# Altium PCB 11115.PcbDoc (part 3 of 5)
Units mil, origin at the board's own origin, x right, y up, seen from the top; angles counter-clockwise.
Board outline 4800 x 3500.1 mil, 4 copper layers (Top Layer, Layer 2, Layer 3, Bottom Layer), stack 61.6 mil thick; 316 components, 224 nets, 954 pads, 623 vias.
Unrouted connection lines stored in the file: 268.
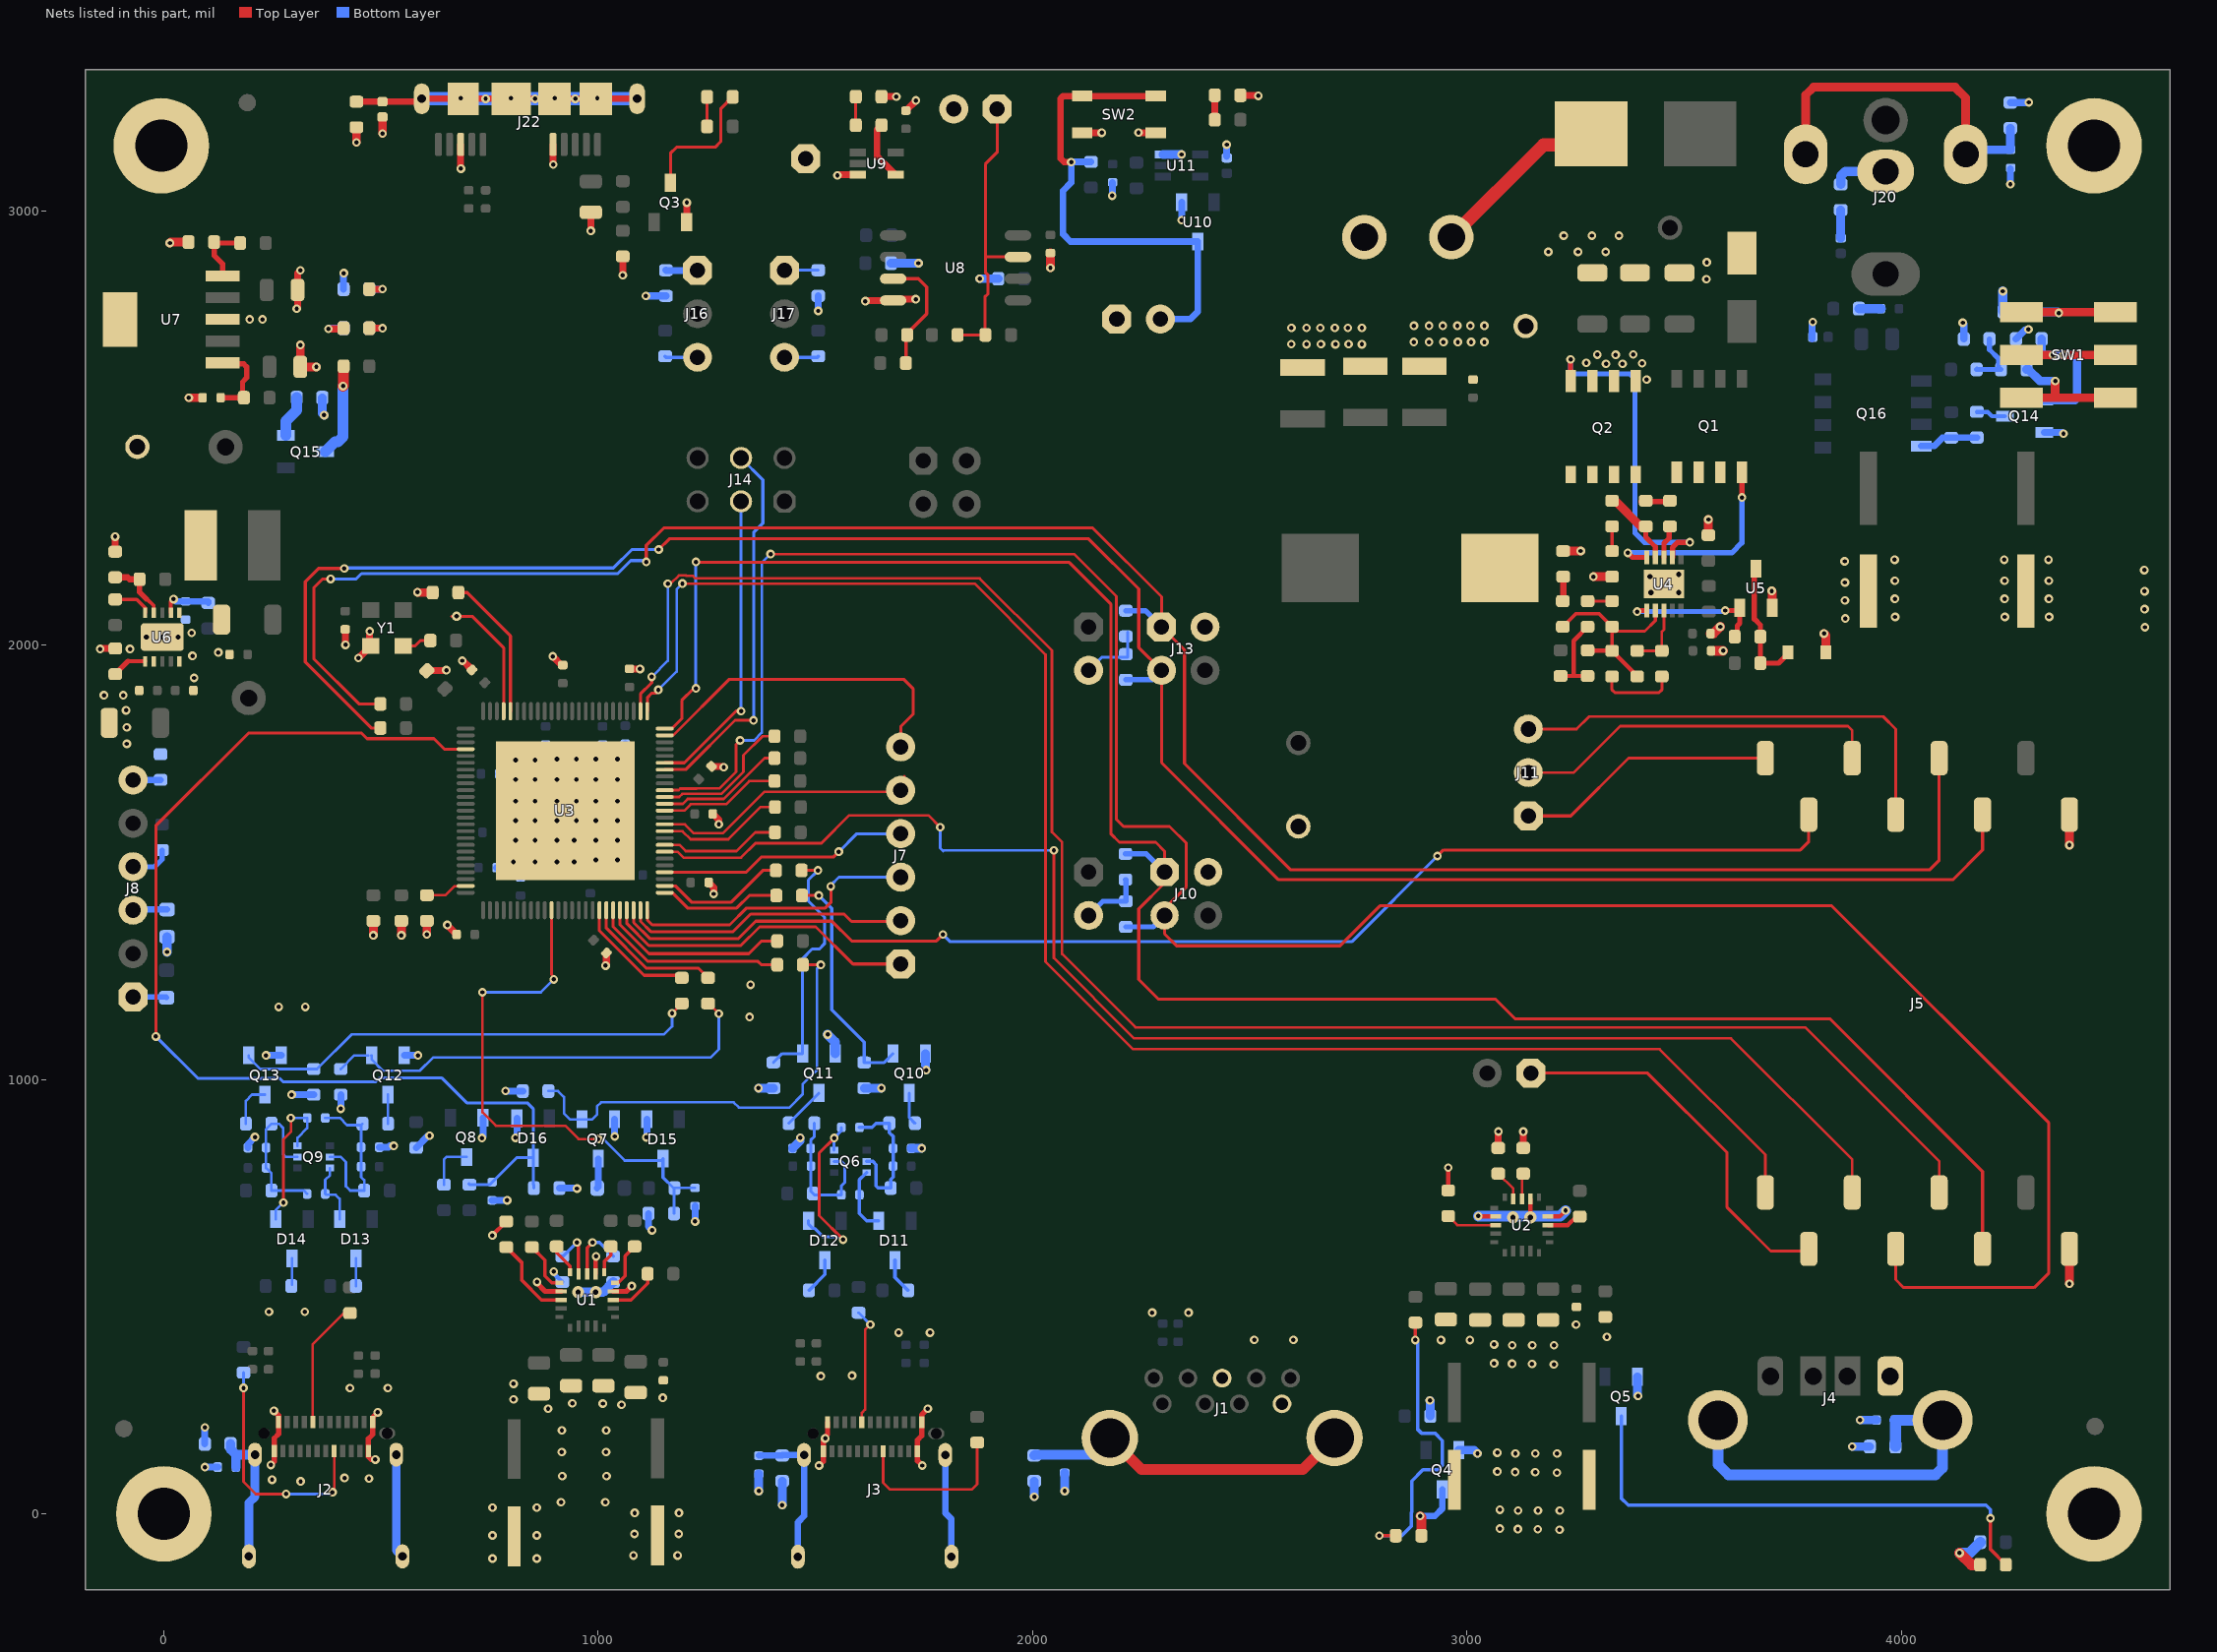
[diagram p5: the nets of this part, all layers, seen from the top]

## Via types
v1: diameter 20, hole 10, Top Layer to Bottom Layer, tented both sides, 576 vias
v2: diameter 23, hole 11, Top Layer to Bottom Layer, 36 vias
v3: diameter 20, hole 12, Top Layer to Bottom Layer, 7 vias
v4: diameter 27.56, hole 11.81, Top Layer to Bottom Layer, 4 vias

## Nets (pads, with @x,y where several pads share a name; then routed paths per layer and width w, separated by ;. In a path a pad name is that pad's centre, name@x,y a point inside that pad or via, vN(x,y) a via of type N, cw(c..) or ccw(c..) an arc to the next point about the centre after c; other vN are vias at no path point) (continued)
DP1_VBUS_MON: C72.1 D16.3 R76.1 R82.2 U3.4 | length 2605
  Top Layer w7: v1(-18.23,1099.34) -18.23,1584.34 195.31,1797.89 455,1797.89 468.07,1784.82 621.82,1784.82 645.77,1760.87 U3.4@695.05,1760.87
  Bottom Layer w7: v1(-18.23,1099.34) 78.56,1002.54 266.75,1002.54 274.56,994.74 487.78,994.74 496.7,1003.66 640.39,1003.66 697.66,946.39 836.77,946.39 850.44,932.72 D16.3@850.44,820.03 ; R76.1@702.08,760.76 R76.1@703.65,759.2 ; R76.1@703.65,758.08 750.3,758.08 C72.1@755.95,763.73 812.25,820.03 D16.3@850.44,820.03 ; R82.2@851.85,750.16 851.85,758.08 850.44,759.49 D16.3@850.44,820.03
DP1_VCONN1: Q13.1 R15.1 R94.2 | length 1093.8
  Top Layer w6: v1(1170.21,1152.37) 1169.7,1152.37 R15.1@1192.54,1175.21
  Bottom Layer w6: Q13.1@195.68,1055.76 195.68,1050.7 222.11,1024.27 R94.2@345.15,1024.27 352.71,1024.27 432.28,1103.83 1151.44,1103.83 1170.21,1122.61 v1(1170.21,1152.37)
DP1_VCONN2: Q12.1 R16.1 R93.2 | length 1034.1
  Top Layer w6: R16.1@1253.06,1175.21 1254.45,1175.21 v1(1277.87,1151.79)
  Bottom Layer w6: R93.2@407.44,1024.27 438.94,1055.76 Q12.1@470.33,1055.76 ; Q12.1@478.31,1055.08 Q12.1@478.99,1055.76 478.99,1045.99 504.69,1020.29 589.62,1020.29 620.03,1050.7 1258.56,1050.7 1277.87,1070 v1(1277.87,1151.79) v1@1277.87,1152.82
DP2_DISCHARGE: Q7.1 R17.1 R92.2 | length 1035.8
  Top Layer w6: R17.1@1471.27,1264.24 v1(1512.67,1264.24)
  Bottom Layer w6: R92.2@885.46,973.67 907.42,973.67 921.31,959.77 921.31,922.12 934.98,908.45 Q7.1@962.83,908.45 986.56,908.45 997.45,919.34 997.45,937.71 1007.19,947.44 1312.07,947.44 1323.83,935.68 1440.67,935.68 1470.9,965.91 1470.9,988.83 1489.95,1007.89 1503.83,1021.77 1503.83,1255.4 v1(1512.67,1264.24)
DP2_VBUS_MON: C70.1 D15.3 R75.2 R80.1 U3.36 | length 1263.9
  Top Layer w6: v1(733.62,1201.02) 733.62,924.26 764.42,893.45 924.57,893.45 954.85,863.17 v1(1000.23,863.17) ; U3.36@892.69,1390 892.69,1242.16 897.72,1237.12 v1(897.72,1230.64)
  Bottom Layer w6: v1(733.62,1201.02) 868.1,1201.02 v1(897.72,1230.64) ; v1(1000.23,863.17) 1011.64,863.17 1061.15,813.66 1145.15,813.66 D15.3@1149.39,817.9 ; R75.2@1174.73,691.52 R80.1@1174.73,748.98 ; R80.1@1175.91,750.16 1176.29,750.54 C70.1@1223.18,750.54
  Bottom Layer w7: D15.3@1149.39,817.9 1149.39,774.32 1174.73,748.98 R80.1@1175.91,750.16
DP2_VCONN1: Q10.1 R22.1 R90.2 | length 541.4
  Top Layer w7: R22.1@1469.24,1423.77 v1(1508.16,1423.77)
  Bottom Layer w7: v1(1508.16,1423.77) 1537.83,1394.09 1537.83,1160.6 1612.48,1085.95 R90.2@1612.48,1039.39 1658.67,1039.39 Q10.1@1678.94,1059.66
DP2_VCONN2: Q11.1 R23.1 R91.2 | length 591.1
  Top Layer w7: R23.1@1468.39,1481.64 v1(1506.19,1481.64)
  Bottom Layer w7: R91.2@1403.43,1039.39 1423.71,1059.66 Q11.1@1470.75,1059.66 1470.75,1278.88 1492.65,1300.78 1509.45,1300.78 1520.87,1312.2 1520.87,1313.74 1521.7,1314.56 1521.7,1373.16 1484.14,1410.71 1484.14,1459.6 v1(1506.19,1481.64)
EARTH_DC: C93.1 J20.0 R102.1 | length 810.9
  Top Layer w20: J20.0@3780.02,3130.32 3780.02,3266.93 3798.08,3285 4124.15,3285 4148.28,3260.87 J20.0@4148.28,3130.32
  Bottom Layer w20: J20.0@4148.28,3130.32 4158.83,3140.87 C93.1@4252,3140.87 4251.28,3141.59 R102.1@4251.28,3190.47
EARTH_P0: C61.2 J22.0 R57.2 | length 1145.1
  Top Layer w15: R57.2@443.5,3251.65 C61.2@503.5,3251.65 587.07,3251.65 J22.0@593.75,3258.33 J22.0@689.42,3258.33 v1(741,3258.33) 799.3,3258.33 J22.0@799.65,3258.33 v1(854.65,3258.33) J22.0@900.05,3258.33 v1(947.45,3258.33) J22.0@994.54,3258.33 J22.0@1089.81,3258.33
  Bottom Layer w30: J22.0@593.75,3258.33 v1(741,3258.33) v1(854.65,3258.33) v1(947.45,3258.33) J22.0@1089.81,3258.33
  other v1: 683.8,3259.39 799.3,3259.39 899.69,3259.39 998.12,3259.39
EARTH_P1: C64.2 J2.25 R65.1 | length 582.6
  Bottom Layer w20: J2.25@195.87,-97.87 195.87,25.15 210.05,39.33 J2.25@210.05,136.39 ; J2.25@535.24,136.39 535.24,-83.69 J2.25@549.42,-97.87
  Bottom Layer w22: R65.1@153.68,160.9 153.68,148.88 166.17,136.39 ; C64.2@165.88,107.76 165.88,136.1 166.17,136.39 ; J2.25@210.05,136.39 166.17,136.39
EARTH_P2: C63.2 J3.25 R63.1 | length 585.1
  Bottom Layer w15: C63.2@1369.87,134.1 1423.28,134.1 R63.1@1423.71,134.53 1424.91,135.73 J3.25@1474.05,135.73 1474.05,-5 1459.87,-19.17 J3.25@1459.87,-98.52 ; J3.25@1799.24,135.73 1799.24,2.17 1813.42,-12.01 J3.25@1813.42,-98.52
EARTH_P3: C62.2 J1.0 R62.2 | length 768.2
  Top Layer w25: J1.0@2177.98,174.73 2250.93,101.79 2622.36,101.79 J1.0@2695.31,174.73
  Bottom Layer w22: R62.2@2004.15,134.53 2005.91,136.28 C62.2@2074.15,136.28 2139.54,136.28 J1.0@2177.98,174.73
EARTH_P4: C65.2 J4.0 R64.2 | length 973.5
  Top Layer w25: J4.0@4095.31,216 J4.0@4134.31,255
  Bottom Layer w25: J4.0@3577.98,216 3577.98,114.09 3602.74,89.33 4078.48,89.33 4095.31,106.16 J4.0@4095.31,216 C65.2@3985.02,216 3986.75,214.27 R64.2@3986.75,155
FB3V3: R109.1 R110.2 U7.5 | length 146.8
  Top Layer w12: U7.5@135.67,2850.34 135.67,2877.74 116.01,2897.4 R110.2@116.01,2928.32 118.21,2926.12 R109.1@175.78,2926.12
FB5V: C52.2 C54.1 R47.2 R48.2 R101.2 U4.2 | length 455.7
  Top Layer w7: 3334.21,2026.88 3334.21,2031.55 3342.34,2031.55 3343.01,2032.23 3409.84,2032.23 3434.02,2056.41 U4.2@3434.02,2080.03
  Top Layer w8: R101.2@3220.84,2042.63 3250.37,2072.16 3304.68,2072.16 C54.1@3334.21,2042.63 ; R47.2@3334.21,1987.21 3334.21,2026.88
  Top Layer w10: R48.2@3277.98,1988.39 3279.16,1987.21 R47.2@3334.21,1987.21 3392.15,1929.27 C52.2@3392.15,1928.15
FBVCORE: R112.1 R119.2 U6.4 | length 149.3
  Top Layer w9: -39.82,2106.31 -38.51,2106.31 -23.09,2090.89 U6.4@-23.09,2074.87
  Top Layer w12: R112.1@-55.69,2151.97 -55.69,2122.18 -39.82,2106.31
  Top Layer w15: R119.2@-111.77,2156.44 -83,2156.44 -78.53,2151.97 R112.1@-55.69,2151.97
GND: C1.2 C2.2 C3.2 C4.2 C5.1 C6.2 C7.1 C8.2 C13.1 C16.1 C17.2 C18.2 C19.1 C20.1 C21.2 C22.2 C23.2 C24.2 C25.2 C26.1 C29.1 C30.2 C31.2 C32.2 C33.1 C34.1 C35.1 C36.1 C37.1 C38.1 C39.1 C40.1 C41.2 C42.2 C43.1 C44.2 C46.1 C47.1 C48.1 C49.1 C50.1 C53.1 C56.1 C59.1 C60.2 C61.1 C62.1 C63.1 C64.1 C65.1 C70.2 C72.2 C78.1 C79.1 C80.1 C81.1 C84.2 C85.2 C86.2 C87.2 C88.2 C89.2 C90.2 C91.2 C92.2 C93.2 C94.1 C95.1 C96.1 C97.1 C98.1 C99.1 C100.2 C101.1 D3.1 D4.1 D6.2 D9.2 D10.2 D15.1 D16.1 J1.4 J1.7 J2.A1 J2.A12 J2.B1 J2.B12 J3.A1 J3.A12 J3.B1 J3.B12 J4.4 J5.8 J5.9 J10.2 J13.2 J18.1 J19.2 J20.2 J21.1 J22.5 J22.8 J23.2 MH1.1 MH2.1 MH3.1 MH4.1 Q2.1 Q2.2 Q2.3 Q3.2 Q4.2 Q5.2 Q7.2 Q8.2 Q10.2 Q11.2 Q12.2 Q13.2 Q14.2 R4.1 R6.1 R11.1 R13.2 R14.2 R19.2 R20.2 R21.2 R31.1 R39.1 R44.2 R45.1 R46.1 R54.1 R57.1 R62.1 R63.2 R64.1 R65.2 R66.1 R71.2 R72.2 R75.1 R82.1 R85.1 R90.1 R91.1 R92.1 R93.1 R94.1 R96.2 R102.2 R103.1 R104.1 R110.1 R113.1 R114.1 R115.1 R116.1 R117.1 R119.1 R125.2 SW2.1 SW2.2 TP2.1 TP6.1 TP8.1 U1.2 U1.14 U1.17 U2.2 U2.14 U2.17 U3.101 U4.11 U5.2 U6.7 U6.10 U6.11 U7.3 U7.6 U8.4 U9.3 U10.1 U11.3 Y1.2 | length 5890.1
  Top Layer w10: v1(756.44,641.21) 788.44,673.22 R6.1@788.44,673.39 ; U1.17@994.33,552.74 994.33,592.2 v1(995.1,592.97) ; R11.1@2957.13,744.72 v1(2957.13,797.22) ; v1(3026.32,685.68) 3027.31,684.69 U2.2@3066.61,684.69 ; v4(3146.33,682.72) U2.17@3146.33,725.04 ; U2.14@3186.69,684.69 3213.52,684.69 v1(3227.3,698.47)
  Top Layer w12: v1(246.65,112.76) 254.54,120.65 J2.B12@254.54,144.65 254.54,174.09 264.38,183.93 J2.A1@264.38,211.58 264.38,226.39 v1(253.65,237.13) ; v1(486.86,125.14) 477.56,125.14 471.07,131.63 J2.B1@471.07,144.65 471.07,173.1 480.91,182.95 J2.A12@480.91,211.58 480.91,222 v1(492.65,233.73) ; v1(859.33,533.91) 859.33,531.08 878.03,512.38 U1.2@914.6,512.38 ; U1.14@1034.68,512.38 1065.27,512.38 v1(1077.44,524.54) ; v1(1508.76,111.24) 1518.54,121.02 J3.B12@1518.54,144 1518.54,173.12 1528.38,182.97 J3.A1@1528.38,210.93 ; v1(1746.17,111.24) 1735.07,122.34 J3.B1@1735.07,144 1735.07,169.96 1744.91,179.81 J3.A12@1744.91,210.93 1744.91,228.05 v1@1759.65,242.79
  Top Layer w16: v1(-146.46,1991.45) -145.31,1992.59 C99.1@-111.77,1992.59 ; v1(-111.93,2250) -111.77,2249.84 R119.1@-111.77,2215.49 ; v1(305.97,2775) 307.94,2776.97 C94.1@307.94,2818.13 307.94,2856.79 v1(314.28,2863.13) ; C38.1@417.75,2036.72 417.75,2026.58 418.46,2025.87 v1(418.46,2000.95) ; v1(448.24,1970.5) 448.65,1970.5 Y1.2@476.54,1998.4 473.99,2000.95 v1(473.99,2032.13) ; D6.2@473.02,2730 v1(503.5,2730) ; R31.1@605.64,1941.32 649.13,1941.32 v1(650.56,1942.75) ; v1(652.76,1355.98) 652.76,1355.43 C22.2@674.18,1334 ; J22.8@683.51,3153.02 683.51,3098.11 v1(684.15,3097.47) ; v1(687.31,1964.45) 687.31,1965.67 C30.2@709.68,1943.3 ; v1(895.6,1974.26) 915.5,1954.36 C31.2@918.59,1954.36 ; J22.5@896.11,3153.02 896.11,3107.5 v1(896.85,3106.76) ; v1(983.13,2954.26) 983.29,2954.42 C59.1@983.29,2996.92 ; v1(1017.17,1262.38) 1019.03,1264.24 C21.2@1019.03,1291.35 ; v1(1056.65,2851.88) R54.1@1056.65,2895.21 ; C32.2@1072.15,1945.64 1096.06,1945.64 v1(1096.39,1945.32) ; Q3.2@1203.97,2974.04 1203.97,3019.14 v1(1204.15,3019.32) ; C23.2@1254.79,1453.7 1266.11,1442.38 v1(1266.11,1427.48) ; C25.2@1261.12,1721.31 1286.96,1721.31 v1(1289.13,1719.14) ; C24.2@1264.04,1611.74 1277.87,1597.91 v1(1277.87,1587.64) ; v1(1550.93,3081.72) 1552.75,3083.54 U9.3@1598.34,3083.54 ; v1(1615.11,2792.15) 1616.95,2793.98 U8.4@1679.05,2793.98 1681.8,2796.73 v1(1731.05,2796.73) ; D9.2@1652.27,3263.18 v1(1686.65,3263.18) ; C60.2@1708.58,3230.87 1731.41,3253.7 v1(1731.41,3254.49) ; SW2.2@2114.5,3179.95 v1(2159.27,3179.95) ; v1(2244.15,3180.28) 2244.48,3179.95 SW2.1@2283.8,3179.95 ; D10.2@2478.68,3266.25 2518.77,3266.25 v1(2520.02,3265) ; R13.2@3072.22,842.49 3072.22,880.04 v1(3072.49,880.31) ; v1(3129.8,880.04) R14.2@3129.8,842.49 3131.32,844.01 R14.2@3131.32,843.48
  Top Layer w20: v1(14.1,2926.12) 16.3,2928.32 R110.1@56.95,2928.32 ; v1(57.62,2570) C96.1@89.24,2570 ; v1(314.28,2691.33) C95.1@314.28,2640.98 v1(351.25,2640.98) ; v1(443.5,3157.73) R57.1@443.5,3192.6 ; v1(482.45,1332.11) R19.2@482.45,1365.34 ; v1(503.5,3178.1) C61.1@503.5,3216.22 ; v1(546.95,1332.11) R20.2@546.95,1365.34 ; v1(584.05,2122.18) 584.9,2121.33 R44.2@619.12,2121.33 ; v1(605.76,1334) R21.2@605.76,1365.34 ; v1(2041.31,2868.79) C56.1@2041.31,2903.08 ; R103.1@3221.78,2216.95 v1(3262.24,2216.95) ; v1(3291.21,2157.89) C44.2@3334.21,2157.89 ; C53.1@3556.07,2253.56 v1(3556.07,2289.55) ; v1(3701.9,2125) 3703.24,2123.65 U5.2@3703.24,2085.94 ; v1(3822.26,2026.88) 3826.74,2022.4 D3.1@3826.74,1983.66 ; v1(4387.22,530) J5.8@4387.22,610 ; v1(4387.22,1540) J5.9@4387.22,1610 ; MH2.1@4404.86,3150 MH2.1@4444.15,3150
  Top Layer w22: C33.1@3561.19,2026.88 3567.48,2026.88 v1(3583.23,2042.63) ; 3572.7,1987.21 v1(3589.86,1987.21)
  Bottom Layer w10: v1(897.72,557.77) 897.72,553.75 R72.2@917.56,533.91
  Bottom Layer w16: v1(94.62,107.76) C64.1@124.15,107.76 ; R65.2@94.62,160.9 v1(94.62,199.1) ; C81.1@193.65,843.13 193.65,851.24 v1(210.05,867.64) ; v1(235.38,1055.76) Q13.2@270.49,1055.76 ; v1(294.28,965.21) R94.1@345.15,965.21 ; v1(407.44,932.72) R93.1@407.44,965.21 ; R46.1@413.97,2820 413.97,2856.19 v1(414.57,2856.79) ; C80.1@496.02,844.26 517.37,844.26 520.43,847.32 v1(529.38,847.32) ; Q12.2@553.79,1055.76 v1(585.38,1055.76) ; R85.1@580.95,842.87 608.72,870.63 v1(611.9,870.63) ; v1(732.45,865.31) 734.78,867.64 Q8.2@734.78,912.28 ; C72.2@755.95,722 v1(790.42,722) ; C87.2@766.17,1487.89 791.72,1487.89 v2(804.82,1500.99) ; C89.2@771.82,1703.98 796.83,1703.98 v2(809.82,1690.99) ; C88.2@775.64,1569.14 793.79,1550.99 v2(809.82,1550.99) ; v1(786.81,973.67) R92.1@826.41,973.67 ; v1(809.82,866.02) 813.04,869.24 D16.1@813.04,910.58 ; C85.2@821.41,1465.5 854.82,1498.91 v2(854.82,1500.99) ; C92.2@879.13,1771.5 879.13,1763.68 v2(904.82,1737.99) ; R82.1@910.9,750.16 950.25,750.16 v1(951.44,748.98) ; C84.2@982.05,1470.62 982.05,1493.22 v2(994.82,1505.99) ; v2(994.82,1737.99) 994.82,1756.13 C91.2@1010.19,1771.5 ; Q7.2@1037.64,908.45 1037.64,869.46 v1(1038.12,868.98) ; v2(1044.82,1505.99) 1060.8,1490.02 C86.2@1060.8,1470.96 ; v2(1044.82,1737.99) 1062.45,1755.62 C90.2@1062.45,1773.01 ; v1(1110.04,2804.25) 1110.14,2804.35 R114.1@1156.06,2804.35 ; v1(1110.71,867.01) 1111.98,868.28 D15.1@1111.98,908.45 ; R75.1@1115.67,691.52 1115.67,661.34 v1(1124.01,653) ; v1(1223.18,673.39) C70.2@1223.18,708.8 ; v1(1506.65,2769.73) R113.1@1506.65,2804.35 ; v1(2183.63,3035) 2183.63,3046.38 2184.47,3047.22 C101.1@2184.47,3065.83 ; v1(2343.37,2978.66) U10.1@2343.37,3020 ; C100.2@2447.14,3125.28 v1(2447.14,3152.75) ; C43.1@3794.46,2705 3794.46,2742.26 v1(3796.67,2744.46) ; v1(4141.65,2742.6) 4144.15,2740.1 R39.1@4144.15,2705 ; v1(4251.28,3061.42) C93.2@4251.28,3097.28 ; R102.2@4251.28,3249.53 4293.24,3249.53 v1(4293.72,3250) ; C50.1@4264.19,2705 4286.35,2727.16 v1(4292.85,2727.16) ; Q14.2@4329.15,2490 4370.73,2490 v1(4373.53,2487.21)
  Bottom Layer w20: R116.1@365.03,2570 365.03,2534.12 v1(369.15,2530) ; v2@805.7,1740.13 v2@807.59,1738.24 ; v2@902.08,1502.02 v2@908.97,1495.13 ; v2@1038.97,1743.08 v2@1043.81,1738.24 ; v2@1043.1,1501.31 v2@1043.81,1502.02 ; v1(1369.15,980.33) R91.1@1403.43,980.33 ; v1(1369.87,52.64) C63.1@1369.87,92.37 ; v1(1423.71,20) R63.2@1423.71,75.47 ; C79.1@1447.53,841.57 1465.17,859.21 v1(1465.17,866.02) ; R90.1@1612.48,980.33 v1(1652.03,980.33) ; R117.1@1674.17,2879.73 v1(1737.39,2879.73) ; C78.1@1720.75,841.57 v1(1744.91,841.57) ; Q10.2@1753.75,1059.66 1753.75,1023.42 v1(1755.4,1021.77) ; v1(1878.38,2843.98) R115.1@1921.05,2843.98 ; v1(2004.15,39.49) R62.1@2004.15,75.47 ; v1(2074.15,52.64) C62.1@2074.15,94.55 ; U11.3@2300.06,3130 v1(2343.37,3130) ; v1(2914.8,261.29) 2915.9,260.19 R66.1@2915.9,225.17 ; Q4.2@2981.25,147.06 3016.63,147.06 v1(3024.55,139.14) ; Q5.2@3392.8,315.73 3392.8,272.82 v1(3394.15,271.47) ; v1(3887.22,155) R64.1@3927.69,155 ; v1(3905.22,216) C65.1@3943.28,216
  Bottom Layer w22: v1(7.55,1293.82) R125.2@7.55,1328.5 ; v4(953.97,510.41) v4(994.33,510.41) 1011.18,510.41 R71.2@1034.68,533.91 ; v1(1528.38,1103.83) 1545.56,1086.66 Q11.2@1545.56,1059.66 ; R104.1@3860.8,3061.42 3860.8,3080 3871.74,3090.95 J20.2@3964.15,3090.95 ; v1(4234,2815) 4234,2769.37 R45.1@4235.53,2767.84
  Bottom Layer w25: v1(3026.32,685.68) 3214.51,685.68 v1(3227.3,698.47)
  other v1: 756.76,-102.83 858.69,-102.83 1081.13,-95.7 1183.06,-95.7 756.76,-49.53 858.69,-49.53 1083.57,-46.1 1185.5,-46.1 3213.49,-36.36 3117.32,-35.12 3163.34,-35.43 3076.04,-33.86 1084.21,2.17 1186.14,2.17 3117.82,7.81 3163.83,7.81 3213.98,7.81 3076.04,9.5 756.76,14.43 858.69,14.43 914.39,26.93 1016.32,26.93 314.99,74.87 249.39,78.54 472.47,81.27 416.19,82.68 917.34,86.77 1019.27,86.77 3207.4,94.97 3111.23,96.21 3157.25,95.9 3069.95,97.47 3111.73,139.14 3157.75,139.14 3207.9,139.14 3069.95,140.83 916.36,142.33 1018.29,142.33 1522.65,173.76 916.57,192.17 1018.5,192.17 884.87,241.93 1758.95,242.09 1053.93,251.07 1010.68,253.99 940.54,254.7 805.33,263.59 1148.7,267.47 428.56,289.77 515.78,289.77 805.33,299.56 1512.65,317.08 1584.65,318.23 3200.24,344.19 3104.07,345.43 3150.09,345.13 3062.79,346.69 3104.57,388.36 3150.58,388.36 3200.74,388.36 3062.79,390.05 2600.62,400.56 2940.55,400.3 3007.04,400.3 2510.55,400.61 3322.4,407.3 1692.05,417.36 1764.05,417.36 3251.42,435.83 2275.55,463.3 2359.31,463.3 242.41,465.43 324.83,465.43 1348.59,1144.01 264.5,1167.19 325.82,1167.19 1350.99,1218.19 -84.93,1772.94 -84.93,1811.06 -86.86,1850.16 -137.78,1884.78 -93.33,1884.78 69.72,1924.76 66.17,1975.58 125.69,1983.38 -77.78,1991.45 64.24,2028.47 4561.07,2041.48 3871.07,2061.59 3986.07,2065.32 4238.61,2065.32 4340.45,2065.32 4560.4,2083.18 3870.4,2103.3 3985.4,2107.02 4237.94,2107.02 4339.78,2107.02 4560.4,2124.49 3870.4,2144.6 3985.4,2148.33 4237.94,2148.33 4339.78,2148.33 4559.72,2173.1 3869.72,2193.21 3984.72,2196.94 4237.26,2196.94 4339.1,2196.94 3413.96,2611.75 3320.39,2648.17 3358.44,2648.17 3403.23,2649.23 3274.94,2650.3 3300.48,2669.12 3342.66,2668.66 3383.12,2669.46 2595.88,2693.18 2631.08,2693.13 2664.19,2693.16 2697.26,2693.13 2727.75,2693.15 2758.36,2693.13 2877.85,2698.21 2913.05,2698.16 2946.16,2698.2 2979.23,2698.16 3009.72,2698.18 3040.33,2698.16 2596.17,2730.57 2631.08,2730.59 2662.72,2730.59 2696.08,2730.59 2726.08,2730.6 2758.36,2730.62 2878.14,2735.6 2913.05,2735.62 2944.69,2735.62 2978.05,2735.62 3008.05,2735.64 3040.33,2735.66 197.61,2750.34 227.33,2750.34 3551.6,2842.77 3552.46,2881.8 3187.66,2905.68 3255.97,2905.66 3319.53,2905.64 3222.85,2943.08 3287.85,2943.08 3350.14,2943.12
  other v2: 904.82,1500.99 944.82,1500.99 854.82,1550.99 904.82,1550.99 944.82,1550.99 994.82,1550.99 1044.82,1550.99 809.82,1595.99 854.82,1595.99 904.82,1595.99 949.82,1595.99 994.82,1595.99 1044.82,1595.99 809.82,1640.99 854.82,1640.99 904.82,1640.99 949.82,1640.99 994.82,1640.99 1044.82,1640.99 854.82,1690.99 904.82,1690.99 949.82,1690.99 994.82,1690.99 1044.82,1690.99 809.82,1735.99 854.82,1735.99 949.82,1737.99
  other v3: -39.82,2018.97 -3.4,2018.97 33.01,2018.97 3423.79,2121.54 3487.84,2121.54 3421.66,2157.89 3487.84,2162.89
  other v4: 3105.98,682.72
L5V: C45.2 L1.1 Q1.1 Q1.2 Q1.3 Q2.5 Q2.6 Q2.7 Q2.8 R35.1 U4.9 | length 182.9
  Top Layer w12: C45.2@3411.8,2273.72 3411.8,2248.75 3434.02,2226.54 U4.9@3434.02,2202.08
  Top Layer w20: R35.1@3334.21,2332.77 3341.38,2332.77 3400.43,2273.72 C45.2@3411.8,2273.72
LVCORE: L2.1 U6.1
MSTR_I2C_CLK: J5.12 J13.1 R30.1 R100.1 | length 5045.2
  Top Layer w7: v1(384.16,2152.66) 365.94,2152.66 345.39,2132.1 345.39,1968.87 449.25,1865 R30.1@498.77,1865 ; v1(1110.77,2191.99) 1110.77,2229.97 1150.81,2270 2138.73,2270 2297.14,2111.59 J13.1@2297.14,2042.28 2350,1989.42 2350,1727.53 2594.74,1482.79 4065.01,1482.79 4087.22,1505 J5.12@4087.22,1740
  Bottom Layer w7: v1(384.16,2152.66) 442.88,2152.66 455.19,2164.97 1045.21,2164.97 1075.24,2195 1107.76,2195 v1(1110.77,2191.99)
  Bottom Layer w12: R100.1@2215,2079.53 2259.9,2079.53 J13.1@2297.14,2042.28
MSTR_I2C_DATA: J5.11 J13.3 R28.1 R99.1 | length 5052.9
  Top Layer w7: v1(415.57,2176.77) 356.28,2176.77 325.82,2146.31 325.82,1961.36 477.55,1809.63 R28.1@498.77,1809.63 ; v1(1139.32,2220.5) 1163.81,2245 2129.4,2245 2244.7,2129.7 2244.7,1994.73 J13.3@2297.14,1942.28 2297.14,1729.54 2566.68,1460 4118.67,1460 4187.22,1528.55 J5.11@4187.22,1610
  Bottom Layer w7: v1(415.57,2176.77) 416.77,2177.97 1035.02,2177.97 1077.56,2220.5 v1(1139.32,2220.5) ; J13.3@2275.33,1920.47 J13.3@2297.14,1942.28
  Bottom Layer w12: R99.1@2215,1920.47 J13.3@2275.33,1920.47
NetC28_2: C28.2 R32.2 | length 50.6
  Bottom Layer w22: R32.2@3902.73,2775 C28.2@3953.28,2775
NetC44_1: C44.1 R35.2 | length 56.8
  Top Layer w8: C44.1@3334.21,2216.95 R35.2@3334.21,2273.72
NetC45_1: C45.1 R40.2 | length 59.9
  Top Layer w12: C45.1@3401.3,2330.6 R40.2@3461.24,2330.6
NetC50_2: C50.2 Q14.1 SW1.2 SW1.5 | length 478.7
  Top Layer w20: SW1.5@4277.02,2668.43 4277.06,2668.38 v1(4349.14,2668.38) ; v1(4373.53,2668.38) 4493.51,2668.38 SW1.2@4493.55,2668.43
  Bottom Layer w20: C50.2@4323.24,2705 4323.24,2674.28 4329.15,2668.38 v1(4349.14,2668.38) v1(4373.53,2668.38) 4397.15,2668.38 4404.86,2660.67 4404.86,2570 4399.66,2564.8 Q14.1@4329.15,2564.8
NetC51_1: C51.1 C52.1 U4.3 | length 151.5
  Top Layer w6: C52.1@3392.15,1987.21 C51.1@3448.88,1987.21 3448.88,2031.36 3453.7,2036.18 U4.3@3453.7,2080.03
NetC51_2: C51.2 R47.1 | length 181.5
  Top Layer w7: R47.1@3334.21,1928.15 3334.21,1897.29 3340.41,1891.09 3442.68,1891.09 3448.88,1897.29 C51.2@3448.88,1928.15
NetC54_2: C54.2 R55.1 | length 56.2
  Top Layer w7: R55.1@3277.98,2101.69 C54.2@3334.21,2101.69
NetC55_1: C55.1 R104.2 | length 64.6
  Bottom Layer w20: C55.1@3860.8,2937.73 R104.2@3860.8,3002.36
NetC71_1: C71.1 C75.1 C79.2 Q6.5 R79.1 R87.2 | length 334.5
  Bottom Layer w7: R87.2@1497.92,899.39 1497.92,869.09 1489.26,860.43 C79.2@1489.26,841.57 1490.05,840.78 C75.1@1490.05,800.8 1490.05,742.19 R79.1@1494.7,737.54 1497.58,734.66 C71.1@1559.89,734.66 1559.89,755.34 1567.75,763.2 1567.75,804.69 1561.07,811.37 Q6.5@1543.35,811.37
NetC71_2: C71.2 D11.3 Q6.3 | length 152.3
  Bottom Layer w8: Q6.3@1618.15,785.78 1601.62,769.24 C71.2@1601.62,734.66 1601.62,691.52 1618.28,674.86 D11.3@1645.95,674.86
NetC73_1: C73.1 C77.1 C81.2 Q9.2 R84.1 R89.2 | length 376.4
  Bottom Layer w6: Q9.2@307.74,821.73 281.49,821.73 274.81,828.42 274.81,888.57 265.07,898.31 R89.2@247.99,898.31 235.38,885.7 C81.2@235.38,843.13 C77.1@235.38,796.73 247.99,784.12 R84.1@247.99,744.31 322.5,744.31 C73.1@330.08,736.73
NetC73_2: C73.2 D13.3 Q9.6 | length 148.7
  Bottom Layer w6: Q9.6@382.55,796.14 382.55,779.85 371.81,769.12 C73.2@371.81,736.73 373.88,734.67 396,734.67 404.93,725.73 D13.3@404.93,678.59
NetC74_1: C74.1 C78.2 C82.1 Q6.2 R78.1 R86.2 | length 336.9
  Bottom Layer w8: C82.1@1601.62,889.73 1630.36,889.73 1640.02,899.39 R86.2@1670.36,899.39 1670.36,877.73 1679.02,869.07 C78.2@1679.02,841.57 C74.1@1679.02,800.8 1679.02,775.29 1673.51,769.78 R78.1@1673.51,750.41 1644.73,750.41 1639.81,755.34 1639.81,804.3 1632.74,811.37 Q6.2@1618.15,811.37
NetC76_1: C76.1 C80.2 C83.1 Q9.5 R83.1 R88.2 | length 391
  Bottom Layer w6: C83.1@371.81,911.73 405.15,911.73 421.62,895.27 R88.2@454.29,895.27 ; Q9.5@382.55,821.73 407.44,821.73 419.17,810.01 419.17,754.3 429.15,744.31 R83.1@461.37,744.31 461.37,768.25 454.29,775.33 C76.1@454.29,799.26 C80.2@454.29,844.26 R88.2@454.29,895.27 ; R88.2@457.34,898.31 R88.2@454.29,895.27
NetC82_2: C82.2 D12.3 Q6.6 | length 432.6
  Top Layer w7: v1(1543.35,865.31) 1508.83,830.79 1508.83,686.63 v1(1563.91,631.55)
  Bottom Layer w7: D12.3@1484.29,674.86 1484.29,666.99 1493.59,657.69 1497.98,657.69 1517.27,638.4 1557.06,638.4 v1(1563.91,631.55) ; Q6.6@1543.35,836.96 v1(1543.35,865.31) 1559.89,881.84 C82.2@1559.89,889.73
NetC83_2: C83.2 D14.3 Q9.3 | length 360.4
  Top Layer w6: v1(275.34,716.88) 275.34,862.43 292.65,879.73 292.65,908.45 290.88,910.21 v1(292.4,911.73)
  Bottom Layer w6: D14.3@257.53,678.59 257.53,699.08 v1(275.34,716.88) ; v1(292.4,911.73) C83.2@330.08,911.73 330.08,888.35 307.74,866.02 Q9.3@307.74,847.32
NetC96_2: C96.2 R106.2 U7.1 | length 184.1
  Top Layer w12: C96.2@131.21,2570 181.32,2570 181.32,2606.03 190.82,2615.54 190.82,2640.99 183.9,2647.91 138.1,2647.91 U7.1@135.67,2650.34
NetC98_2: C98.2 R111.1 U6.2 | length 119.2
  Top Layer w9: U6.2@16.28,2074.87 16.28,2099.94 v1(22.65,2106.31)
  Bottom Layer w15: v1(22.65,2106.31) 28.13,2100.83 C98.2@50.23,2100.83 102.23,2100.83 R111.1@102.23,2097.53
NetC99_2: C99.2 U6.6 | length 81.2
  Top Layer w9: -82.24,1963.06 U6.6@-42.77,1963.06
  Top Layer w12: C99.2@-111.77,1933.53 -82.24,1963.06
NetD1_1: D1.1 R61.2 | length 116.4
  Top Layer w25: v1(4134.31,-90) 4135.06,-90 4162.06,-117 D1.1@4181.76,-117
  Bottom Layer w25: v1(4134.31,-90) 4156.76,-90 R61.2@4181.76,-65
NetD1_2: D1.2 Q5.3 | length 1191.4
  Top Layer w8: v1(4205.22,-10) 4205.22,-81.41 D1.2@4240.81,-117
  Bottom Layer w8: Q5.3@3355.4,225.17 3355.4,36.25 3371.65,20 4195.22,20 4205.22,10 v1(4205.22,-10)
NetD2_1: D2.1 R3.2 | length 683.7
  Top Layer w8: v1(2798.44,-50.27) D2.1@2836.37,-50.27 ; v1(2881.26,400.25) 2881.65,400.64 R3.2@2881.65,440.47
  Bottom Layer w8: v1(2798.44,-50.27) 2850.15,-50.27 2872.65,-27.77 2872.65,3.62 2872.98,3.96 2872.98,75.87 2898.9,101.79 2933.9,101.79 2943.85,111.74 2943.85,168.28 2926.18,185.96 2895.53,185.96 2886.37,195.12 2886.37,395.14 v1(2881.26,400.25)
NetD2_2: D2.2 Q4.3 | length 148.9
  Top Layer w22: v1(2892.65,-5) 2895.43,-7.78 D2.2@2895.43,-50.27
  Bottom Layer w15: v1(2892.65,-5) 2926.4,-5 2943.85,12.45 Q4.3@2943.85,56.51
NetD3_2: D3.2 R41.1 R42.2 U5.3 | length 300.4
  Top Layer w12: U5.3@3665.84,2176.49 3661.91,2172.55 3661.91,2060.35 3675.69,2046.57 R42.2@3675.69,2019.8 R41.1@3675.69,1958.86 3717.37,1958.86 3738.95,1980.44 D3.2@3738.95,1983.66
NetD5_2: D5.2 R46.2 | length 60.9
  Top Layer w16: D5.2@473.02,2820 v1(503.5,2820)
  Bottom Layer w16: R46.2@473.02,2820 v1(503.5,2820)
NetD6_1: D6.1 R105.1 | length 70.9
  Top Layer w16: v1(379.19,2728.44) 412.41,2728.44 D6.1@413.97,2730
  Bottom Layer w16: v1(379.19,2728.44) 380.75,2730 R105.1@413.97,2730
NetD7_2: D7.2 Q15.3 | length 217.9
  Top Layer w25: v1(412.61,2596.61) 413.97,2597.97 D7.2@413.97,2642.37
  Bottom Layer w25: Q15.3@371.66,2445.74 394.79,2468.87 401.19,2468.87 412.61,2480.29 v1(412.61,2596.61)
NetD8_1: D8.1 R58.2 | length 68
  Top Layer w7: R58.2@1250.82,3194.68 D8.1@1250.82,3262.64
NetD8_2: D8.2 Q3.3 | length 328.2
  Top Layer w7: Q3.3@1166.57,3064.59 1166.57,3132.77 1180.46,3146.65 1269.27,3146.65 1282.05,3159.43 1282.05,3234.81 D8.2@1309.87,3262.64 1308.23,3262.64 1296.09,3250.5
NetD9_1: D9.1 R59.2 | length 65.7
  Top Layer w7: R59.2@1593.21,3197.47 D9.1@1593.21,3263.18
NetD10_1: D10.1 R60.2 | length 56.3
  Top Layer w15: R60.2@2419.62,3210 D10.1@2419.62,3266.25
NetD11_1: D11.1 R69.1 | length 82.3
  Bottom Layer w8: D11.1@1683.35,584.31 1683.35,544.9 R69.1@1713.66,514.58
NetD12_1: D12.1 R70.1 | length 84.8
  Bottom Layer w8: R70.1@1485.32,514.58 1521.7,550.96 D12.1@1521.7,584.31
NetD13_1: D13.1 R73.1 | length 63.2
  Bottom Layer w6: R73.1@442.34,524.83 D13.1@442.34,588.04
NetD14_1: D14.1 R74.1 | length 60.9
  Bottom Layer w6: R74.1@294.93,527.19 D14.1@294.93,588.04
NetF1_2: F1.2 J19.1 | length 422.3
  Top Layer w30: J19.1@2964.15,2939.69 3176.35,3151.89 F1.2@3298.56,3151.89
NetJ2_A5: J2.A5 R2.2 | length 294.3
  Top Layer w6: J2.A5@343.12,211.58 343.12,390.77 414.57,462.23 R2.2@428.68,462.23
NetJ2_B5: J2.B5 R67.2 | length 566
  Top Layer w6: v1(183.65,290) 183.65,73.73 211.65,45.73 v1(281.65,45.73) ; v1(388.32,49.75) 392.33,53.76 J2.B5@392.33,144.65
  Bottom Layer w6: v1(183.65,290) R67.2@183.65,325.2 ; v1(281.65,45.73) 384.3,45.73 v1(388.32,49.75)
NetJ3_A5: J3.A5 R68.2 | length 271.7
  Top Layer w6: J3.A5@1607.12,210.93 1607.12,232.74 1614.65,240.27 1614.65,423.45 v1(1626.8,435.61)
  Bottom Layer w6: R68.2@1599.46,463.17 1626.8,435.82 v1(1626.8,435.61)
NetJ3_B5: J3.B5 R1.2 | length 396.1
  Top Layer w6: J3.B5@1656.33,144 1656.33,71.5 1671.75,56.08 1860.46,56.08 1872.65,68.26 R1.2@1872.65,164.15
NetJ5_2: J5.2 J6.1 | length 886.1
  Top Layer w7: J6.1@3147.02,1015 3415.99,1015 3599.15,831.84 3599.15,705.55 3699.74,604.96 3782.18,604.96 J5.2@3787.22,610
NetJ5_13: J5.13 J11.3 | length 1066.7
  Top Layer w6: J11.3@3141.41,1807.09 3252.41,1807.09 3281.16,1835.84 3958.47,1835.84 3987.22,1807.09 J5.13@3987.22,1610
NetJ5_14: J5.14 J11.2 | length 858
  Top Layer w6: J11.2@3141.41,1707.09 3246.24,1707.09 3352.98,1813.83 3877.19,1813.83 3887.22,1803.8 J5.14@3887.22,1740
NetJ5_16: J5.16 J11.1 | length 600.9
  Top Layer w7: J11.1@3141.41,1607.09 3239.27,1607.09 3372.18,1740 J5.16@3687.22,1740
NetJ8_1: J8.1 R124.2 | length 78.1
  Bottom Layer w12: J8.1@-70.85,1190 5.14,1190 R124.2@6.64,1188.5
NetJ8_3: J8.3 R125.1 | length 79
  Bottom Layer w15: J8.3@-70.85,1390 -69.36,1391.5 R125.1@7.55,1391.5
NetJ8_4: J8.4 R98.2 | length 103.2
  Bottom Layer w12: J8.4@-65.33,1484.48 J8.4@-70.85,1490 -21.04,1490 -3.84,1507.2 R98.2@-3.84,1528.49
NetJ8_6: J8.6 R96.1 | length 63.3
  Bottom Layer w15: J8.6@-70.85,1690 R96.1@-7.55,1690
NetJ9_2: J9.2 R95.2 R97.2 | length 149.7
  Bottom Layer w12: J9.2@2129.15,1377.79 2161.92,1410.57 R95.2@2215,1410.57 2215,1459.62 R97.2@2214.15,1460.47
NetJ12_2: J12.2 R99.2 R100.2 | length 160.3
  Bottom Layer w7: J12.2@2129.15,1942.28 2159.01,1972.14 2218.77,1972.14 R100.2@2218.77,2030.47
NetJ14_2: J14.2 U3.70 | length 707.9
  Top Layer w7: U3.70@1153.32,1729.37 1198.73,1729.37 1317.62,1848.27 v1(1328.96,1848.27)
  Bottom Layer w7: v1(1328.96,1848.27) 1328.96,2325 J14.2@1328.96,2331.29
NetJ14_5: J14.5 U3.69 | length 885.4
  Top Layer w7: U3.69@1153.32,1713.62 1201.57,1713.62 1315.14,1827.2 v1(1357.9,1827.2)
  Bottom Layer w7: J14.5@1328.96,2431.29 1379.26,2380.99 1379.26,2280.88 1357.9,2259.52 v1(1357.9,1827.2)
NetJ16_1: J16.1 R114.2 | length 73
  Bottom Layer w16: R114.2@1156.06,2863.4 1156.34,2863.13 J16.1@1228.96,2863.13
NetJ16_3: J16.3 R108.2 | length 75.5
  Bottom Layer w8: R108.2@1154.3,2665.21 1156.38,2663.13 J16.3@1228.96,2663.13
NetJ17_1: J17.1 R113.2 | length 77.8
  Bottom Layer w7: J17.1@1428.96,2863.13 1429.24,2863.4 R113.2@1506.65,2863.4
NetJ17_3: J17.3 R107.2 | length 78.5
  Bottom Layer w8: J17.3@1428.96,2663.13 1504.57,2663.13 R107.2@1506.65,2665.21
NetJ18_2: J18.2 R121.1 SW2.3 SW2.4 U10.3 | length 1178.9
  Top Layer w15: v1(2089.15,3112.28) 2072.78,3112.28 2064.78,3120.28 2064.78,3258.78 2070.61,3264.6 SW2.4@2114.5,3264.6 SW2.3@2283.8,3264.6
  Bottom Layer w15: R121.1@2134.47,3113.07 2089.93,3113.07 v1(2089.15,3112.28) 2089.15,3065.27 2070.61,3046.73 2070.61,2946.16 2087.32,2929.45 U10.3@2380.77,2929.45 2380.77,2768.59 2363.05,2750.87 J18.2@2294.15,2750.87
NetJ23_1: J23.1 R51.1 R52.1 U8.7 | length 676.5
  Top Layer w7: R51.1@1827.5,2714.67 R52.1@1891.52,2714.67 1890.42,2715.77 1890.42,2802.06 1897.88,2809.52 1897.88,2852.06 1891.52,2858.42 1891.52,2893.98 ; J23.1@1918.69,3234.8 1918.69,3134.72 1891.52,3107.56 1891.52,2893.98 ; U8.7@1966.45,2893.98 1891.52,2893.98
NetQ1_4: Q1.4 U4.10 | length 490.3
  Top Layer w12: v1(3370.5,2212.78) 3381.2,2202.08 U4.10@3414.33,2202.08 ; v1(3633.23,2340.36) Q1.4@3633.23,2398.24
  Bottom Layer w12: v1@3369.32,2213.2 v1@3374.52,2208 ; v1(3370.5,2212.78) 3610.17,2212.78 3633.23,2235.84 v1(3633.23,2340.36)
NetQ2_4: Q2.4 U4.7 | length 788.6
  Top Layer w12: Q2.4@3238.82,2608.44 v1(3238.82,2658.19) ; U4.7@3473.39,2202.08 3473.39,2225.15 3485.33,2237.1 v1(3513.14,2237.1)
  Bottom Layer w12: v1(3238.82,2658.19) 3238.82,2633.31 3247.44,2624.69 3375.55,2624.69 3387,2613.24 3387,2258.56 3408.47,2237.1 v1(3513.14,2237.1)
NetQ7_3: Q7.3 R81.1 | length 68.8
  Bottom Layer w15: R81.1@997.69,750.16 1000.23,752.7 Q7.3@1000.23,817.9
NetQ8_3: Q8.3 R77.1 | length 112.8
  Bottom Layer w6: R77.1@644.91,758.09 644.91,816.08 650.56,821.73 Q8.3@697.38,821.73
NetQ10_3: Q10.3 R86.1 | length 75.4
  Bottom Layer w7: Q10.3@1716.34,969.11 1716.34,947.44 1716.06,947.16 1716.06,912.74 R86.1@1729.41,899.39
NetQ11_3: Q11.3 R87.1 | length 98.4
  Bottom Layer w7: R87.1@1438.86,899.39 1508.16,968.68 Q11.3@1508.16,969.11
NetQ12_3: Q12.3 R88.1 | length 66.9
  Bottom Layer w6: R88.1@516.39,898.31 Q12.3@516.39,965.21
NetQ13_3: Q13.3 R89.1 | length 102.7
  Bottom Layer w6: R89.1@188.94,898.31 188.94,951.02 203.12,965.21 Q13.3@233.08,965.21
NetQ14_3: Q14.3 R38.1 | length 68.5
  Bottom Layer w10: R38.1@4174.19,2537.24 4199.23,2537.24 4209.07,2527.4 Q14.3@4238.6,2527.4
NetQ15_2: Q15.2 R116.2 | length 97.2
  Bottom Layer w25: Q15.2@281.11,2483.14 281.11,2516.26 305.97,2541.12 R116.2@305.97,2570
NetQ16_4: Q16.4 R33.1 R38.2 | length 136.3
  Bottom Layer w15: Q16.4@4046.04,2458.47 4075.69,2458.47 4094.98,2477.76 R33.1@4115.13,2477.76 4115.56,2478.19 R38.2@4174.19,2478.19
NetR5_2: R5.2 U1.13 | length 117.1
  Top Layer w8: U1.13@1034.68,492.7 1076.05,492.7 1113.91,530.55 R5.2@1113.91,552.74
NetR6_2: R6.2 U1.3 | length 200.2
  Top Layer w8: R6.2@788.44,614.33 824.71,578.06 824.71,537.63 869.65,492.7 U1.3@914.6,492.7
NetR7_2: R7.2 U1.1 | length 118.7
  Top Layer w8: R7.2@847.44,614.33 877.72,584.04 877.72,547.57 887.66,537.63 893.23,532.07 U1.1@910.67,532.07
NetR8_2: R8.2 U1.20 | length 71.9
  Top Layer w8: R8.2@904.51,615.8 904.51,600.89 904.59,600.89 935.27,570.21 U1.20@935.27,556.67
NetR9_1: R9.1 U1.16 | length 65.4
  Top Layer w8: U1.16@1014.01,556.67 1014.01,580.43 1029.08,595.5 R9.1@1029.08,615.8
NetR10_1: R10.1 U1.15 | length 106.8
  Top Layer w8: U1.15@1038.62,532.06 1045.91,532.06 1061.81,547.96 1061.81,593.72 R10.1@1083.89,615.8
NetR11_2: R11.2 U2.3 | length 118
  Top Layer w6: R11.2@2957.13,685.67 2977.8,665 U2.3@3066.61,665
NetR12_2: R12.2 U2.13 | length 73.8
  Top Layer w10: U2.13@3186.69,665 3232.62,665 R12.2@3252.3,684.69
NetR13_1: R13.1 U2.19 | length 72.8
  Top Layer w6: R13.1@3072.22,783.44 3106.96,748.69 U2.19@3106.96,725.04
NetR14_1: R14.1 U2.18 | length 59.7
  Top Layer w6: U2.18@3126.65,725.04 3126.65,780.29 R14.1@3129.8,783.44
NetR21_1: R21.1 U3.24 | length 98.2
  Top Layer w6: R21.1@605.76,1424.39 648.52,1424.39 669.51,1445.38 694.52,1445.38 U3.24@695.05,1445.91
NetR26_1: R26.1 U3.63 | length 281.1
  Top Layer w6: U3.63@1153.32,1619.13 1198.06,1619.13 1212.88,1633.96 1241.78,1633.96 1241.95,1634.13 1294.62,1634.13 1347.91,1687.42 R26.1@1406.12,1687.42
NetR27_1: R27.1 U3.64 | length 296.4
  Top Layer w6: U3.64@1153.32,1634.88 1195.16,1634.88 1206.24,1645.96 1236.81,1645.96 1236.98,1646.13 1289.27,1646.13 1383.29,1740.16 R27.1@1406.12,1740.16
NetR29_1: R29.1 U3.65 | length 333.7
  Top Layer w6: U3.65@1153.32,1650.63 1186.61,1650.63 1193.94,1657.96 1231.84,1657.96 1232.01,1658.13 1284.3,1658.13 1334.96,1708.8 1334.35,1709.41 1334.35,1746.52 1378.38,1790.55 R29.1@1406.12,1790.55
NetR34_1: R34.1 R37.1 R39.2 | length 135.3
  Bottom Layer w12: R34.1@4174.19,2635.51 R34.1@4173.68,2635 R37.1@4224.15,2635 ; R39.2@4203.21,2705 4203.21,2680.75 4224.15,2659.8 R37.1@4224.15,2635 ; R37.1@4229.62,2635 R37.1@4224.15,2635
NetR36_1: R36.1 Y1.3 | length 71
  Top Layer w7: Y1.3@551.35,1998.4 578.35,1998.4 590.78,2010.83 R36.1@613.62,2010.83 ; R36.1@613.62,1998.4 614,1998.4 R36.1@616.24,2000.64
NetR37_2: R37.2 SW1.1 SW1.4 | length 331.8
  Top Layer w20: SW1.4@4277.02,2570 4354.54,2570 ; v1(4354.54,2608.44) 4354.54,2570 ; SW1.1@4493.55,2570 4354.54,2570
  Bottom Layer w20: R37.2@4288.68,2635 4292.85,2635 4319.41,2608.44 v1(4354.54,2608.44)
NetR40_1: R40.1 U4.8 | length 66.2
  Top Layer w12: U4.8@3453.7,2202.08 3453.7,2234.98 3465.84,2247.12 R40.1@3465.84,2263.24
NetR42_1: R42.1 U4.1 U5.1 | length 337.4
  Top Layer w12: v1(3392.15,2077.51) 3394.68,2080.03 U4.1@3414.33,2080.03 ; v1(3594.98,2080.03) 3622.54,2080.03 U5.1@3628.44,2085.94 3628.44,2050.51 3622.54,2044.6 3622.54,2025.7 R42.1@3616.63,2019.8
  Bottom Layer w12: v1@3388.82,2077.51 v1(3392.15,2077.51) 3592.45,2077.51 v1(3594.98,2080.03)
NetR43_1: R43.1 R48.1 R55.2 | length 188.8
  Top Layer w10: R43.1@3215.84,1929.33 3245.84,1929.33 ; R48.1@3277.98,1929.33 3245.84,1929.33 ; R55.2@3277.98,2042.63 3245.84,2010.49 3245.84,1929.33
NetR44_1: R44.1 U3.96 | length 334.6
  Top Layer w7: R44.1@678.17,2121.33 698.37,2121.33 798.2,2021.5 U3.96@798.2,1848.27
NetR45_2: R45.2 SW1.3 SW1.6 | length 286.1
  Top Layer w20: SW1.6@4277.02,2766.85 SW1.3@4493.55,2766.85
  Bottom Layer w20: R45.2@4294.59,2767.84 4360.16,2767.84 v1(4363,2765)
NetR49_1: R49.1 R50.1 U8.3 | length 283.3
  Top Layer w8: U8.3@1677.05,2841.98 U8.3@1679.05,2843.98 1737.39,2843.98 1756.65,2824.73 1756.65,2763.13 1711.32,2717.8 R50.1@1711.32,2714.67 1708.58,2711.92 R49.1@1708.58,2649.73
NetR59_1: R59.1 U9.4 | length 136.6
  Top Layer w15: R59.1@1652.27,3197.47 1641.65,3186.85 1641.65,3126.3 1684.4,3083.54 U9.4@1684.95,3083.54
NetR71_1: R71.1 U1.18 | length 138.1
  Top Layer w8: U1.18@974.64,552.74 974.64,612.46 v1(987.05,624.86)
  Bottom Layer w8: v1(987.05,624.86) 1002.79,624.86 R71.1@1034.68,592.97
NetR72_1: R72.1 U1.19 | length 120.7
  Top Layer w8: v1(951.44,624.86) 954.96,621.33 U1.19@954.96,552.74
  Bottom Layer w8: R72.1@917.56,592.97 919.55,592.97 v1(951.44,624.86)
NetR101_1: R101.1 R103.2 | length 57.5
  Top Layer w8: R101.1@3220.84,2101.69 R101.1@3221.78,2101.69
  Top Layer w15: R101.1@3220.84,2101.69 3221.78,2102.62 R103.2@3221.78,2157.89
NetR122_2: R122.2 U6.5 | length 88.2
  Top Layer w8: R122.2@-111.77,2105.49 -62.32,2105.49 -42.77,2085.94 U6.5@-42.77,2074.87
NetTP4_1: TP4.1 U3.97 | length 296.1
  Top Layer w7: 662.37,2066.78 709.92,2066.78 782.45,1994.25 U3.97@782.45,1848.27
PF2: R15.2 U3.43 | length 281.8
  Top Layer w7: U3.43@1002.92,1390 1002.92,1342.73 1105.65,1240 1186.8,1240 R15.2@1192.54,1234.26
PF3: R16.2 U3.44 | length 323.1
  Top Layer w7: U3.44@1018.67,1390 1018.67,1348.64 1110.77,1256.54 1230.78,1256.54 R16.2@1253.06,1234.26
PF4: R17.2 U3.45 | length 452
  Top Layer w7: U3.45@1034.42,1390 1034.42,1352.27 1114.82,1271.87 1367.93,1271.87 1375.56,1264.24 R17.2@1412.22,1264.24
PF5: R18.2 U3.46 | length 435.3
  Top Layer w7: U3.46@1050.17,1390 1050.17,1356.57 1116.93,1289.8 1347.07,1289.8 1376.38,1319.11 R18.2@1412.22,1319.11
PF6: J7.1 U3.47 | length 736
  Top Layer w7: U3.47@1065.91,1390 1066.25,1389.67 1066.25,1358.87 1116.72,1308.4 1328.57,1308.4 1371.83,1351.66 1500.96,1351.66 1586.63,1265.99 J7.1@1696.66,1265.99
PF7: J5.15 U3.48 | length 2955.9
  Top Layer w7: U3.48@1081.66,1390 1082,1389.67 1082,1361.51 1119.5,1324 1322.09,1324 1362.75,1364.66 1538.04,1364.66 1583.6,1319.11 1778.76,1319.11 v1(1793.65,1334) ; v1(2932.33,1514.73) 2946.14,1528.55 3767.85,1528.55 3787.22,1547.92 J5.15@3787.22,1610
  Bottom Layer w7: v1(1793.65,1334) 1810.48,1317.17 2734.77,1317.17 v1(2932.33,1514.73)
PF8: J7.2 U3.49 | length 659.1
  Top Layer w7: U3.49@1097.41,1390 1097.74,1389.67 1097.74,1364.14 1121.22,1340.67 1310.89,1340.67 1351.26,1381.04 1566.35,1381.04 1583.24,1364.14 1694.81,1364.14 J7.2@1696.66,1365.99
PF9: J7.3 U3.50 | length 679.7
  Top Layer w7: U3.50@1113.16,1390 1113.16,1367.48 1124.66,1355.98 1302.89,1355.98 1341.77,1394.86 1522.95,1394.86 1535.66,1407.58 v1(1535.66,1444.63)
  Bottom Layer w7: v1(1535.66,1444.63) 1535.66,1447.49 1554.16,1465.99 J7.3@1696.66,1465.99
PF10: R22.2 U3.51 | length 283.5
  Top Layer w7: U3.51@1153.32,1430.16 1170.72,1430.16 1206.02,1394.86 1319,1394.86 1347.91,1423.77 R22.2@1410.19,1423.77
PF11: R23.2 U3.52 | length 302.3
  Top Layer w7: U3.52@1153.32,1445.91 1177.84,1445.91 1215.88,1407.86 1305.48,1407.86 1379.26,1481.64 R23.2@1409.34,1481.64
PF12: J7.4 U3.54 | length 580
  Top Layer w7: U3.54@1153.32,1477.4 1340.65,1477.4 1375.34,1512.09 1541.51,1512.09 v1(1554.06,1524.65)
  Bottom Layer w7: v1(1554.06,1524.65) 1595.41,1565.99 J7.4@1696.66,1565.99
PF14: J5.3 U3.57 | length 3358.6
  Top Layer w6: U3.57@1153.32,1524.65 1182.98,1524.65 1196.63,1510.99 1328.89,1510.99 1362.23,1544.34 1514.01,1544.34 1578.12,1608.46 1760.14,1608.46 v1(1787.61,1580.99) ; v1(2049.15,1527.61) 2049.25,1527.51 2049.25,1280.06 2234.31,1095 3608.01,1095 3887.22,815.79 J5.3@3887.22,740
  Bottom Layer w6: v1(1787.61,1580.99) 1787.61,1532.79 1794.41,1525.99 1796.02,1527.61 v1(2049.15,1527.61)
PF15: R24.2 U3.58 | length 277.8
  Top Layer w6: U3.58@1153.32,1540.39 1187.17,1540.39 1201.57,1525.99 1318.77,1525.99 1361.92,1569.14 R24.2@1407.26,1569.14
PF17: R25.2 U3.60 | length 292.3
  Top Layer w6: U3.60@1153.32,1571.89 1194.36,1571.89 1212.85,1553.39 1299.83,1553.39 1373.92,1627.49 R25.2@1407.26,1627.49
PF18: J7.5 U3.61 | length 614.4
  Top Layer w6: U3.61@1153.32,1587.64 1199.62,1587.64 1220.21,1567.05 1287.38,1567.05 1382.95,1662.62 1669.27,1662.62 J7.5@1704.88,1698.23
PF19: J5.4 J10.3 R95.1 U3.66 | length 5680.2
  Top Layer w6: U3.66@1153.32,1666.38 1185.38,1666.38 1188.97,1669.96 1226.87,1669.96 1227.04,1670.13 1278.96,1670.13 1317.62,1708.8 1317.62,1771.57 v1(1326.92,1780.87) ; v1(1397.15,2210) 2095.58,2210 2193.21,2112.36
  Top Layer w7: 2193.21,2112.36 2193.21,1599.21 2209.63,1582.79 2315.56,1582.79 2354.15,1544.21 2354.15,1444.15 2304.15,1394.15 J10.3@2304.15,1377.79 2304.15,1335.41 2331.53,1308.04 2708.04,1308.04 2800,1400 3840,1400 4340,900 4340,555 4306,521 4005.61,521 3987.22,539.39 J5.4@3987.22,610
  Bottom Layer w6: v1(1326.92,1780.87) 1359.06,1780.87 1376.9,1798.7 1376.9,2189.75 v1(1397.15,2210)
  Bottom Layer w12: R95.1@2215,1351.51 2277.87,1351.51 J10.3@2304.15,1377.79
PF26: J5.6 J10.1 R97.1 U3.75 | length 4813.4
  Top Layer w7: U3.75@1162.36,1808.11 1170.04,1808.11 1192.54,1830.6 1192.54,1873.05 1220.34,1900.85 v1(1225.01,1900.85) ; v1(1225.01,2191.99) 1226.5,2190.5 2084.71,2190.5 2180.21,2095 2180.21,1565.99 2199.9,1546.31 2283.69,1546.31 2304.15,1525.85 J10.1@2304.15,1477.79 2304.15,1452.37 2244.7,1392.92 2244.7,1230.3 2290,1185 3065.77,1185 3110.77,1140 3835.61,1140 4187.22,788.39 J5.6@4187.22,610
  Bottom Layer w7: v1(1225.01,1900.85) v1(1225.01,2191.99)
  Bottom Layer w12: R97.1@2214.15,1519.53 2262.41,1519.53 J10.1@2304.15,1477.79
PF27: J5.1 U3.76 | length 3870.4
  Top Layer w6: v1(1193.94,2141.9) 1866.57,2141.9 2030.15,1978.32 2030.15,1271.64 2231.79,1070 3444.15,1070 3687.22,826.93 J5.1@3687.22,740
  Top Layer w7: U3.76@1113.16,1848.27 1113.16,1879.21 1123.87,1889.92 1133.35,1889.92 v1@1139.32,1895.89
  Bottom Layer w6: v1(1138.61,1897.26) 1180.87,1939.52 1180.87,2128.81 v1(1193.94,2141.9)
PF28: J5.5 U3.77 | length 4280.7
  Top Layer w6: v1(1160.4,2141.88) 1167.04,2141.88 1186.07,2160.9 1201.81,2160.9 1202.71,2159.99 1217.67,2159.99 1223.77,2153.9 1878.38,2153.9 2044.56,1987.71 2044.56,1569.89 2068.15,1546.31 2068.15,1288.82 2236.97,1120 3779.15,1120 4087.22,811.93 J5.5@4087.22,740
  Top Layer w7: U3.77@1097.41,1848.27 1097.41,1887.68 1123.32,1913.58 v1(1123.32,1927.38)
  Bottom Layer w6: v1(1123.32,1927.38) 1160.4,1964.46 v1(1160.4,2141.88)
PF29: J7.6 U3.74 | length 780
  Top Layer w7: U3.74@1153.32,1792.36 1172.68,1792.36 1301.96,1921.65 1703.44,1921.65 1725.02,1900.07 1725.02,1840.93 1696.66,1812.57 J7.6@1696.66,1765.99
